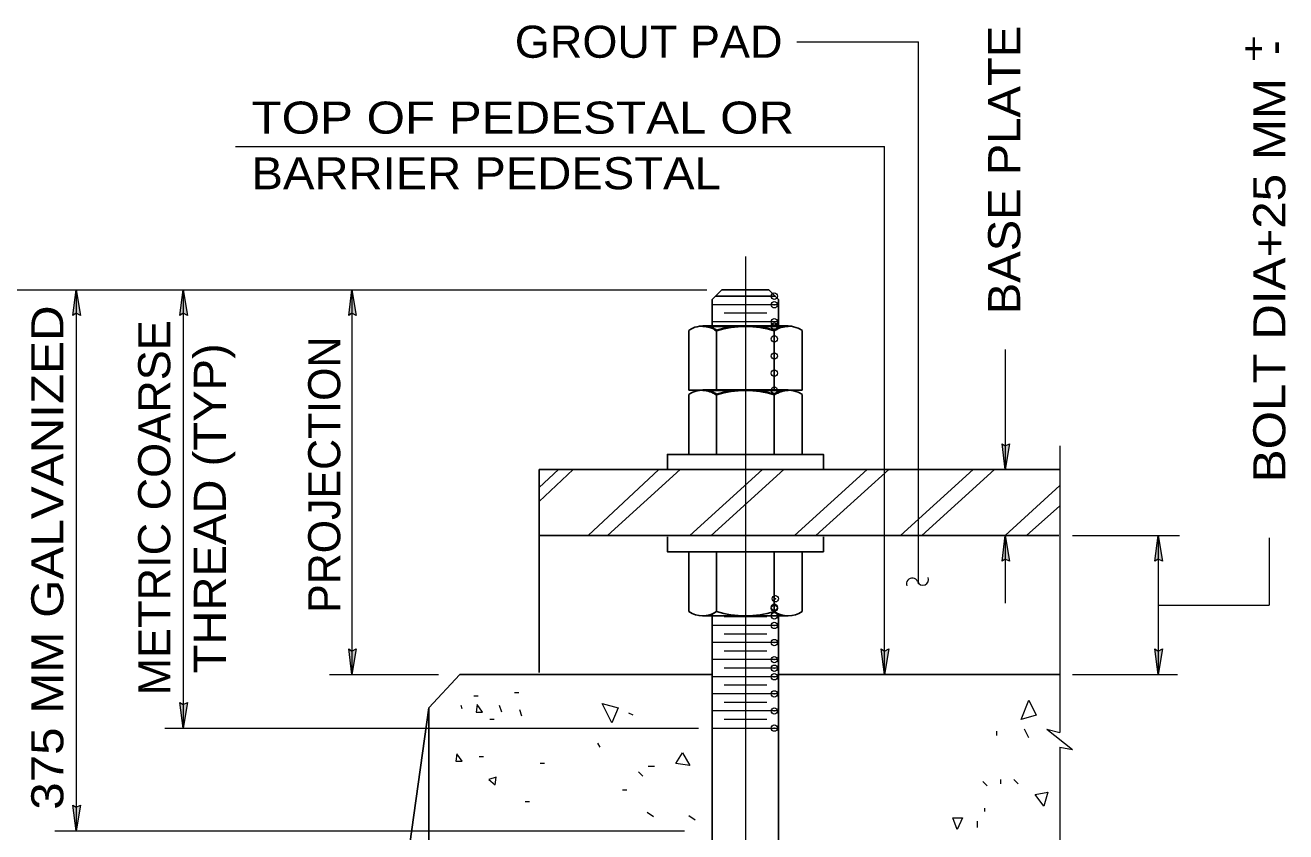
# Model space of a CAD drawing. Extents: x 312601.859 to 312602.7, y 144420.109 to 144420.704.
# Drawn here: x 312602.0589 to 312602.1768, y 144420.3257 to 144420.4011 of the extents above; entities that cross this region are included whole.
import ezdxf
from ezdxf.enums import TextEntityAlignment as Align

# ---------------------------------------------------------------- set-up
doc = ezdxf.new("R2010")
doc.units = 0
doc.header["$LTSCALE"] = 0.0012
doc.header["$PDMODE"] = 32
doc.header["$PDSIZE"] = 0.0006
doc.linetypes.add('DOT_DASHED', pattern=[7.7, 5, -1.2, 0.3, -1.2])
doc.linetypes.add('LONG_DASHED', pattern=[7.5, 6, -1.5])
for name, color, linetype, lineweight in [('1', 7, 'Continuous', 13), ('2', 7, 'Continuous', 13), ('39', 7, 'Continuous', 13)]:
    doc.layers.add(name, color=color, linetype=linetype, lineweight=lineweight)
doc.layers.add('6', color=7, linetype='Continuous')

msp = doc.modelspace()

# ---------------------------------------------------------------- hatches: boundary and pattern name
at = {"layer": '39'}
for points in [[(312602.0637, 144420.3742), (312602.0634, 144420.374), (312602.0637, 144420.3764), (312602.0641, 144420.374)], [(312602.0737, 144420.3742), (312602.0734, 144420.374), (312602.0737, 144420.3764), (312602.0741, 144420.374)], [(312602.0895, 144420.3742), (312602.0892, 144420.374), (312602.0895, 144420.3764), (312602.0899, 144420.374)], [(312602.1506, 144420.3618), (312602.151, 144420.362), (312602.1506, 144420.3596), (312602.1503, 144420.362)], [(312602.1506, 144420.3512), (312602.1503, 144420.351), (312602.1506, 144420.3534), (312602.151, 144420.351)], [(312602.1649, 144420.3512), (312602.1646, 144420.351), (312602.1649, 144420.3534), (312602.1653, 144420.351)], [(312602.0895, 144420.3426), (312602.0899, 144420.3428), (312602.0895, 144420.3404), (312602.0892, 144420.3428)], [(312602.1393, 144420.3426), (312602.1397, 144420.3428), (312602.1393, 144420.3404), (312602.139, 144420.3428)], [(312602.1649, 144420.3426), (312602.1653, 144420.3428), (312602.1649, 144420.3404), (312602.1646, 144420.3428)], [(312602.0737, 144420.3376), (312602.0741, 144420.3378), (312602.0737, 144420.3354), (312602.0734, 144420.3378)], [(312602.0637, 144420.328), (312602.0641, 144420.3282), (312602.0637, 144420.3258), (312602.0634, 144420.3282)]]:
    msp.add_hatch(color=256, dxfattribs=at).paths.add_polyline_path(points)

# ---------------------------------------------------------------- linework, layer by layer
at = {"layer": '1'}
for p, q in [((312602.1311, 144420.3996), (312602.1425, 144420.3996)), ((312602.1425, 144420.3489), (312602.1425, 144420.3996)), ((312602.0786, 144420.3898), (312602.1393, 144420.3898)), ((312602.1393, 144420.3404), (312602.1393, 144420.3898)), ((312602.0511, 144420.3764), (312602.1223, 144420.3764)), ((312602.0634, 144420.3764), (312602.1227, 144420.3764)), ((312602.0637, 144420.3764), (312602.0637, 144420.3258)), ((312602.0737, 144420.3764), (312602.0737, 144420.3354)), ((312602.0895, 144420.3764), (312602.0895, 144420.3404)), ((312602.1294, 144420.375), (312602.1232, 144420.375)), ((312602.1283, 144420.3742), (312602.1243, 144420.3742)), ((312602.1294, 144420.3734), (312602.1232, 144420.3734)), ((312602.129, 144420.373), (312602.1288, 144420.373)), ((312602.1506, 144420.3708), (312602.1506, 144420.3596)), ((312602.129, 144420.367), (312602.1288, 144420.367)), ((312602.1557, 144420.3618), (312602.1557, 144420.335)), ((312602.107, 144420.3566), (312602.1102, 144420.3596)), ((312602.107, 144420.3579), (312602.1088, 144420.3596)), ((312602.1116, 144420.3534), (312602.1182, 144420.3596)), ((312602.1134, 144420.3534), (312602.1202, 144420.3596)), ((312602.1211, 144420.3534), (312602.1279, 144420.3596)), ((312602.1231, 144420.3534), (312602.1299, 144420.3596)), ((312602.1309, 144420.3534), (312602.1377, 144420.3596)), ((312602.1329, 144420.3534), (312602.1397, 144420.3596)), ((312602.1408, 144420.3534), (312602.1476, 144420.3596)), ((312602.1428, 144420.3534), (312602.1496, 144420.3596)), ((312602.1506, 144420.3534), (312602.1557, 144420.3581)), ((312602.1526, 144420.3534), (312602.1557, 144420.3562)), ((312602.1336, 144420.3534), (312602.1263, 144420.3534)), ((312602.1506, 144420.3534), (312602.1506, 144420.3471)), ((312602.1569, 144420.3534), (312602.1669, 144420.3534)), ((312602.1649, 144420.3534), (312602.1649, 144420.3404)), ((312602.1753, 144420.3532), (312602.1753, 144420.3469)), ((312602.1283, 144420.3458), (312602.1243, 144420.3458)), ((312602.1294, 144420.345), (312602.1232, 144420.345)), ((312602.1294, 144420.3434), (312602.1232, 144420.3434)), ((312602.1283, 144420.3442), (312602.1243, 144420.3442)), ((312602.1283, 144420.3426), (312602.1243, 144420.3426)), ((312602.1294, 144420.3418), (312602.1232, 144420.3418)), ((312602.0874, 144420.3404), (312602.0976, 144420.3404)), ((312602.1294, 144420.3402), (312602.1232, 144420.3402)), ((312602.1294, 144420.341), (312602.1243, 144420.341)), ((312602.1569, 144420.3404), (312602.1667, 144420.3404)), ((312602.1051, 144420.3387), (312602.1047, 144420.3387)), ((312602.1283, 144420.3394), (312602.1243, 144420.3394)), ((312602.0998, 144420.3372), (312602.0997, 144420.3375)), ((312602.1013, 144420.3384), (312602.1009, 144420.3384)), ((312602.1035, 144420.3369), (312602.1033, 144420.3375)), ((312602.1294, 144420.3386), (312602.1232, 144420.3386)), ((312602.1283, 144420.3378), (312602.1243, 144420.3378)), ((312602.1054, 144420.3365), (312602.1052, 144420.3371)), ((312602.1158, 144420.3366), (312602.1154, 144420.3368)), ((312602.1294, 144420.337), (312602.1232, 144420.337)), ((312602.072, 144420.3354), (312602.1219, 144420.3354)), ((312602.1028, 144420.3362), (312602.1024, 144420.3362)), ((312602.1232, 144420.3354), (312602.1294, 144420.3354)), ((312602.1283, 144420.3362), (312602.1243, 144420.3362)), ((312602.1528, 144420.3345), (312602.1524, 144420.3353)), ((312602.1545, 144420.3353), (312602.1569, 144420.3334)), ((312602.1545, 144420.3353), (312602.1557, 144420.335)), ((312602.1127, 144420.3336), (312602.1125, 144420.334)), ((312602.1498, 144420.3347), (312602.1498, 144420.3351)), ((312602.1557, 144420.3336), (312602.1557, 144420.3031)), ((312602.1557, 144420.3336), (312602.1569, 144420.3334)), ((312602.1018, 144420.3327), (312602.1014, 144420.3327)), ((312602.1075, 144420.3321), (312602.1071, 144420.3321)), ((312602.1178, 144420.3318), (312602.1172, 144420.3318)), ((312602.1167, 144420.3309), (312602.1163, 144420.3313)), ((312602.1489, 144420.33), (312602.1485, 144420.3304)), ((312602.1502, 144420.3302), (312602.1502, 144420.3306)), ((312602.1518, 144420.3302), (312602.1514, 144420.3306)), ((312602.1152, 144420.3296), (312602.1148, 144420.3296)), ((312602.1061, 144420.3285), (312602.1057, 144420.3285)), ((312602.1177, 144420.3271), (312602.1171, 144420.3275)), ((312602.1216, 144420.3268), (312602.121, 144420.3272)), ((312602.1487, 144420.3276), (312602.1487, 144420.3279)), ((312602.0617, 144420.3258), (312602.1206, 144420.3258)), ((312602.148, 144420.3261), (312602.148, 144420.3267))]:
    msp.add_line(p, q, dxfattribs=at)
at = {"layer": '1', "linetype": 'DOT_DASHED'}
msp.add_line((312602.1263, 144420.3795), (312602.1263, 144420.2731), dxfattribs=at)
at = {"layer": '1', "lineweight": 25}
for p, q in [((312602.1232, 144420.3755), (312602.1241, 144420.3764)), ((312602.1241, 144420.3764), (312602.1285, 144420.3764)), ((312602.1294, 144420.3755), (312602.1285, 144420.3764)), ((312602.1232, 144420.3755), (312602.1232, 144420.373)), ((312602.1291, 144420.3758), (312602.1235, 144420.3758)), ((312602.1294, 144420.3755), (312602.1294, 144420.373)), ((312602.121, 144420.3726), (312602.121, 144420.367)), ((312602.1236, 144420.3726), (312602.1236, 144420.367)), ((312602.129, 144420.3726), (312602.129, 144420.367)), ((312602.1316, 144420.3726), (312602.1316, 144420.367)), ((312602.121, 144420.367), (312602.1316, 144420.367)), ((312602.121, 144420.3666), (312602.121, 144420.361)), ((312602.1236, 144420.3666), (312602.1236, 144420.361)), ((312602.129, 144420.3666), (312602.129, 144420.361)), ((312602.1316, 144420.3666), (312602.1316, 144420.361)), ((312602.107, 144420.3596), (312602.1557, 144420.3596)), ((312602.107, 144420.3406), (312602.107, 144420.3596)), ((312602.107, 144420.3534), (312602.1556, 144420.3534)), ((312602.119, 144420.3534), (312602.1263, 144420.3534)), ((312602.121, 144420.3463), (312602.121, 144420.3519)), ((312602.1236, 144420.3463), (312602.1236, 144420.3519)), ((312602.129, 144420.3463), (312602.129, 144420.3518)), ((312602.1316, 144420.3463), (312602.1316, 144420.3518)), ((312602.1303, 144420.3459), (312602.1223, 144420.3459)), ((312602.1302, 144420.3459), (312602.1223, 144420.3459)), ((312602.1232, 144420.346), (312602.1232, 144420.3245)), ((312602.1294, 144420.346), (312602.1294, 144420.3245)), ((312602.0967, 144420.3373), (312602.0996, 144420.3404)), ((312602.0996, 144420.3404), (312602.1232, 144420.3404)), ((312602.1294, 144420.3404), (312602.1557, 144420.3404)), ((312602.0967, 144420.3373), (312602.0967, 144420.2695))]:
    msp.add_line(p, q, dxfattribs=at)
at = {"layer": '1', "lineweight": 35}
for p, q in [((312602.1302, 144420.373), (312602.1223, 144420.373)), ((312602.1302, 144420.367), (312602.1223, 144420.367))]:
    msp.add_line(p, q, dxfattribs=at)
at = {"layer": '1', "linetype": 'LONG_DASHED', "lineweight": 25}
msp.add_line((312602.0872, 144420.2695), (312602.0967, 144420.3373), dxfattribs=at)
at = {"layer": '1', "lineweight": 25}
for points in [[(312602.119, 144420.3596), (312602.119, 144420.361), (312602.1263, 144420.361), (312602.1336, 144420.361), (312602.1336, 144420.3596)], [(312602.119, 144420.3533), (312602.119, 144420.3519), (312602.1263, 144420.3519), (312602.1336, 144420.3519), (312602.1336, 144420.3533)]]:
    msp.add_lwpolyline(points, dxfattribs=at)
at = {"layer": '1'}
for points in [[(312602.1129, 144420.3377), (312602.1144, 144420.3373), (312602.1138, 144420.3359)], [(312602.1528, 144420.338), (312602.1535, 144420.3366), (312602.1521, 144420.3362)], [(312602.1198, 144420.3321), (312602.1204, 144420.3331), (312602.1211, 144420.3319)], [(312602.1534, 144420.3292), (312602.1546, 144420.3294), (312602.1542, 144420.3281)], [(312602.1457, 144420.327), (312602.1466, 144420.327), (312602.1461, 144420.3259)]]:
    msp.add_lwpolyline(points, close=True, dxfattribs=at)
at = {"layer": '1', "lineweight": 25}
for centre, radius, start, end in [((312602.1223, 144420.3707), 0.0023, 81.174, 124.41739), ((312602.1303, 144420.3707), 0.0023, 55.58261, 98.78454), ((312602.1223, 144420.3647), 0.0023, 81.174, 124.41739), ((312602.1303, 144420.3647), 0.0023, 55.58261, 98.78454), ((312602.1223, 144420.3482), 0.0023, 235.58261, 304.37164), ((312602.1223, 144420.3482), 0.0023, 270, 304.37164), ((312602.1263, 144420.355212), 0.0093125, 253.14606, 286.87109), ((312602.1303, 144420.3482), 0.0023, 235.69352, 304.41739), ((312602.1303, 144420.3482), 0.0023, 235.69352, 270)]:
    msp.add_arc(centre, radius, start, end, dxfattribs=at)
at = {"layer": '1', "lineweight": 35}
for centre, radius, start, end in [((312602.1223, 144420.3707), 0.0023, 55.62836, 90), ((312602.1263, 144420.363688), 0.0093125, 73.12891, 106.85394), ((312602.1303, 144420.3707), 0.0023, 90, 124.30648), ((312602.1223, 144420.3647), 0.0023, 55.62836, 90), ((312602.1263, 144420.357688), 0.0093125, 73.12891, 106.85394), ((312602.1303, 144420.3647), 0.0023, 90, 124.30648)]:
    msp.add_arc(centre, radius, start, end, dxfattribs=at)
at = {"layer": '1'}
for centre, radius, start, end in [((312602.1344, 144420.3598), 0.0132004, 102.23769, 102.24633), ((312602.1344, 144420.3538), 0.0132004, 102.23769, 102.24633), ((312602.1263, 144420.355212), 0.0093125, 253.14606, 286.87109), ((312602.1262, 144420.3591), 0.0132004, 282.23769, 282.24633)]:
    msp.add_arc(centre, radius, start, end, dxfattribs=at)
for p in [(312602.129, 144420.3758), (312602.129, 144420.375), (312602.129, 144420.3734), (312602.129, 144420.373), (312602.129, 144420.3718), (312602.129, 144420.3702), (312602.129, 144420.3686), (312602.129, 144420.367), (312602.129, 144420.3467), (312602.1291, 144420.3475), (312602.129, 144420.3466), (312602.129, 144420.3459), (312602.129, 144420.345), (312602.129, 144420.3434), (312602.129, 144420.3418), (312602.129, 144420.341), (312602.129, 144420.3402), (312602.129, 144420.3386), (312602.129, 144420.337), (312602.129, 144420.3354)]:
    msp.add_point(p, dxfattribs=at)
at = {"layer": '2', "lineweight": 25}
for p, q in [((312602.1258, 144420.373), (312602.1267, 144420.373)), ((312602.1258, 144420.367), (312602.1267, 144420.367))]:
    msp.add_line(p, q, dxfattribs=at)
at = {"layer": '2'}
msp.add_line((312602.1649, 144420.3469), (312602.1753, 144420.3469), dxfattribs=at)
for points in [[(312602.1012, 144420.3376), (312602.1011, 144420.3369), (312602.1017, 144420.3369)], [(312602.0993, 144420.333), (312602.0992, 144420.3323), (312602.0998, 144420.3323)], [(312602.103, 144420.3308), (312602.1023, 144420.3306), (312602.1029, 144420.3301)]]:
    msp.add_lwpolyline(points, close=True, dxfattribs=at)
for centre, start, end in [((312602.1419, 144420.3489), 21.80141, 201.80141), ((312602.1429, 144420.3493), 201.80141, 21.80141)]:
    msp.add_arc(centre, 0.0005385, start, end, dxfattribs=at)
at = {"layer": '39'}
for points in [[(312602.0637, 144420.3742), (312602.0634, 144420.374), (312602.0637, 144420.3764), (312602.0641, 144420.374)], [(312602.0737, 144420.3742), (312602.0734, 144420.374), (312602.0737, 144420.3764), (312602.0741, 144420.374)], [(312602.0895, 144420.3742), (312602.0892, 144420.374), (312602.0895, 144420.3764), (312602.0899, 144420.374)], [(312602.1506, 144420.3618), (312602.151, 144420.362), (312602.1506, 144420.3596), (312602.1503, 144420.362)], [(312602.1506, 144420.3512), (312602.1503, 144420.351), (312602.1506, 144420.3534), (312602.151, 144420.351)], [(312602.1649, 144420.3512), (312602.1646, 144420.351), (312602.1649, 144420.3534), (312602.1653, 144420.351)], [(312602.0895, 144420.3426), (312602.0899, 144420.3428), (312602.0895, 144420.3404), (312602.0892, 144420.3428)], [(312602.1393, 144420.3426), (312602.1397, 144420.3428), (312602.1393, 144420.3404), (312602.139, 144420.3428)], [(312602.1649, 144420.3426), (312602.1653, 144420.3428), (312602.1649, 144420.3404), (312602.1646, 144420.3428)], [(312602.0737, 144420.3376), (312602.0741, 144420.3378), (312602.0737, 144420.3354), (312602.0734, 144420.3378)], [(312602.0637, 144420.328), (312602.0641, 144420.3282), (312602.0637, 144420.3258), (312602.0634, 144420.3282)]]:
    msp.add_lwpolyline(points, close=True, dxfattribs=at)

# ---------------------------------------------------------------- texts
at = {"layer": '2', "width": 1.05}
msp.add_text('GROUT PAD', height=0.003, dxfattribs=at).set_placement((312602.11725, 144420.3981), align=Align.CENTER)
at = {"layer": '2'}
for s, width, p in [('BASE PLATE', 1.1, (312602.152, 144420.3876)), ('BOLT DIA+25 MM', 1.15, (312602.1768, 144420.3773)), ('375 MM GALVANIZED', 1.15, (312602.0625, 144420.35135)), ('METRIC COARSE', 1.05, (312602.0725, 144420.356)), ('THREAD (TYP)', 1.1, (312602.0777, 144420.35595))]:
    msp.add_text(s, height=0.003, rotation=90, dxfattribs=dict(at, width=width)).set_placement(p, align=Align.CENTER)
for s, width, p in [('TOP OF PEDESTAL OR', 1.15, (312602.0801, 144420.391)), ('BARRIER PEDESTAL', 1.1, (312602.0801, 144420.3858))]:
    msp.add_text(s, height=0.003, dxfattribs=dict(at, width=width)).set_placement(p)
msp.add_text('PROJECTION', height=0.002998, rotation=90, dxfattribs=at).set_placement((312602.0884, 144420.3591), align=Align.CENTER)
at = {"layer": '6', "width": 0.8}
msp.add_text('+', height=0.003, dxfattribs=at).set_placement((312602.17385, 144420.3975), align=Align.CENTER)
at = {"layer": '6'}
msp.add_text('-', height=0.003, rotation=90, dxfattribs=at).set_placement((312602.1772, 144420.39905), align=Align.CENTER)

doc.saveas('drawing.dxf')
